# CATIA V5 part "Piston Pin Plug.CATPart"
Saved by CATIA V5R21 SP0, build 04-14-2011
Part number: Piston Pin Plug
Bounding box of the stored display mesh (mm): x -11 to 11, y -10.833 to 10.833, z -15 to 0
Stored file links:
  D:\CATIA V5R21 E-RESOURCES\CATIA-V5R21\catia-v5r21-Prts\c13_catia_v5r21_prt\c13_catia_v5r21_figr_13-41\Part & Asm files\Piston Pin Plug.CATPart
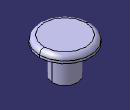
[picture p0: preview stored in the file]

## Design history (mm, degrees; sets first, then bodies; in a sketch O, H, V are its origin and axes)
Body1 (main body)
  Sketch1 on xy-plane, origin (0, 0, 0), H (1, 0, 0), V (0, 1, 0)
    circle A1 centre (0, 0) radius 11
    circle A2 centre (0, 0) radius 5.5
    radius A2 = 5.5
    radius A1 = 11
  MultiPad1: profile Sketch1, domains (length 15; length 3)
  Fillet1: radius 2, on 1 edge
